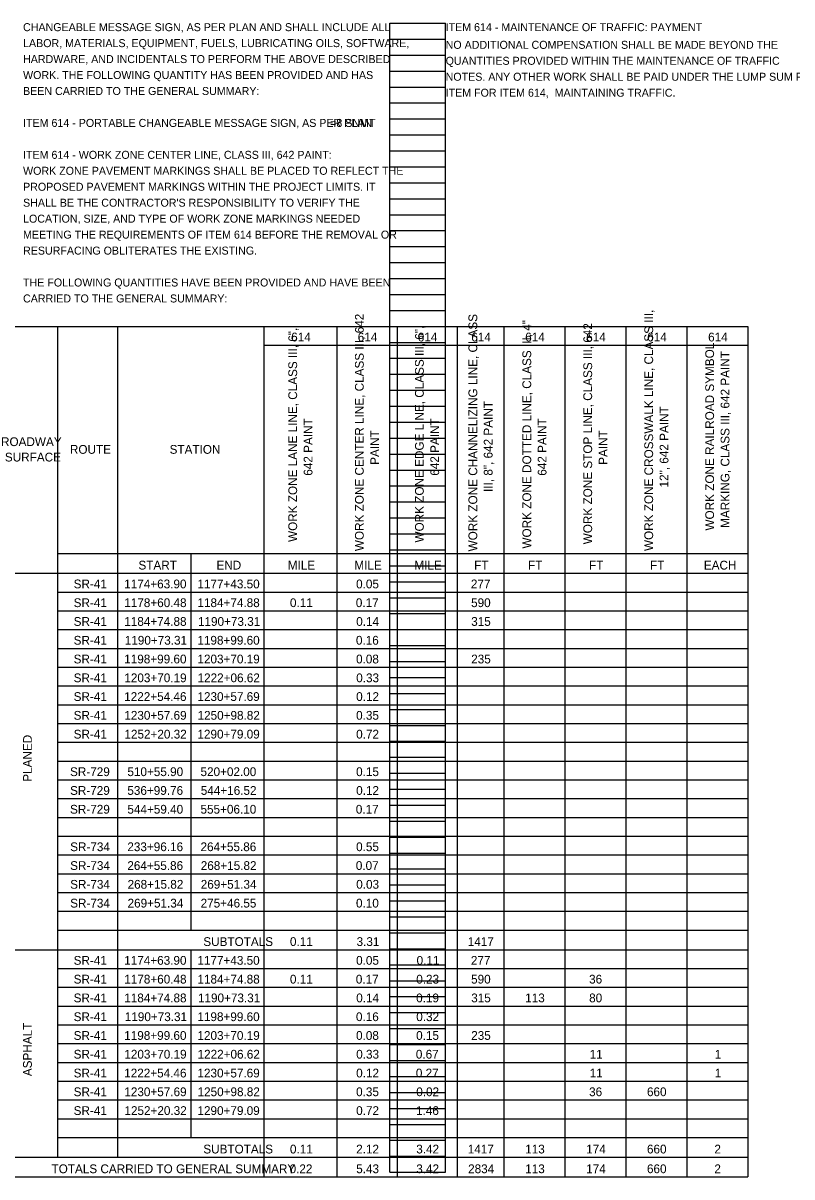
# Model space of a CAD drawing. Extents: x 0 to 37668, y -5 to 18949.
# Drawn here: x 37646.22 to 37659.72, y 18868.37 to 18888.61 of the extents above; entities that cross this region are included whole.
import ezdxf

# ---------------------------------------------------------------- set-up
doc = ezdxf.new("R2010")
doc.units = 0
doc.layers.add('SH_Data', color=7, linetype='Continuous')
doc.layers.add('SH_Text', color=7, linetype='Continuous')

msp = doc.modelspace()

# ---------------------------------------------------------------- linework, layer by layer
at = {"layer": 'SH_Data'}
for p, q in [((37652.661, 18868.45), (37652.661, 18888.61)), ((37652.661, 18888.61), (37653.641, 18888.61)), ((37653.641, 18868.45), (37653.641, 18888.61)), ((37652.661, 18888.33), (37653.641, 18888.33)), ((37652.661, 18888.05), (37653.641, 18888.05)), ((37652.661, 18887.77), (37653.641, 18887.77)), ((37652.661, 18887.49), (37653.641, 18887.49)), ((37652.661, 18887.21), (37653.641, 18887.21)), ((37652.661, 18886.93), (37653.641, 18886.93)), ((37652.661, 18886.65), (37653.641, 18886.65)), ((37652.661, 18886.37), (37653.641, 18886.37)), ((37652.661, 18886.09), (37653.641, 18886.09)), ((37652.661, 18885.81), (37653.641, 18885.81)), ((37652.661, 18885.53), (37653.641, 18885.53)), ((37652.661, 18885.25), (37653.641, 18885.25)), ((37652.661, 18884.97), (37653.641, 18884.97)), ((37652.661, 18884.69), (37653.641, 18884.69)), ((37652.661, 18884.41), (37653.641, 18884.41)), ((37652.661, 18884.13), (37653.641, 18884.13)), ((37652.661, 18883.85), (37653.641, 18883.85)), ((37652.661, 18883.57), (37653.641, 18883.57)), ((37652.661, 18883.29), (37653.641, 18883.29)), ((37652.661, 18883.01), (37653.641, 18883.01)), ((37652.661, 18882.73), (37653.641, 18882.73)), ((37652.661, 18882.45), (37653.641, 18882.45)), ((37652.661, 18882.17), (37653.641, 18882.17)), ((37652.661, 18881.89), (37653.641, 18881.89)), ((37652.661, 18881.61), (37653.641, 18881.61)), ((37652.661, 18881.33), (37653.641, 18881.33)), ((37652.661, 18881.05), (37653.641, 18881.05)), ((37652.661, 18880.77), (37653.641, 18880.77)), ((37652.661, 18880.49), (37653.641, 18880.49)), ((37652.661, 18880.21), (37653.641, 18880.21)), ((37652.661, 18879.93), (37653.641, 18879.93)), ((37652.661, 18879.65), (37653.641, 18879.65)), ((37652.661, 18879.37), (37653.641, 18879.37)), ((37652.661, 18879.09), (37653.641, 18879.09)), ((37652.661, 18878.81), (37653.641, 18878.81)), ((37652.661, 18878.53), (37653.641, 18878.53)), ((37652.661, 18878.25), (37653.641, 18878.25)), ((37652.661, 18877.97), (37653.641, 18877.97)), ((37652.661, 18877.69), (37653.641, 18877.69)), ((37652.661, 18877.41), (37653.641, 18877.41)), ((37652.661, 18877.13), (37653.641, 18877.13)), ((37652.661, 18876.85), (37653.641, 18876.85)), ((37652.661, 18876.57), (37653.641, 18876.57)), ((37652.661, 18876.29), (37653.641, 18876.29)), ((37652.661, 18876.01), (37653.641, 18876.01)), ((37652.661, 18875.73), (37653.641, 18875.73)), ((37652.661, 18875.45), (37653.641, 18875.45)), ((37652.661, 18875.17), (37653.641, 18875.17)), ((37652.661, 18874.89), (37653.641, 18874.89)), ((37652.661, 18874.61), (37653.641, 18874.61)), ((37652.661, 18874.33), (37653.641, 18874.33)), ((37652.661, 18874.05), (37653.641, 18874.05)), ((37652.661, 18873.77), (37653.641, 18873.77)), ((37652.661, 18873.49), (37653.641, 18873.49)), ((37652.661, 18873.21), (37653.641, 18873.21)), ((37652.661, 18872.93), (37653.641, 18872.93)), ((37652.661, 18872.65), (37653.641, 18872.65)), ((37652.661, 18872.37), (37653.641, 18872.37)), ((37652.661, 18872.09), (37653.641, 18872.09)), ((37652.661, 18871.81), (37653.641, 18871.81)), ((37652.661, 18871.53), (37653.641, 18871.53)), ((37652.661, 18871.25), (37653.641, 18871.25)), ((37652.661, 18870.97), (37653.641, 18870.97)), ((37652.661, 18870.69), (37653.641, 18870.69)), ((37652.661, 18870.41), (37653.641, 18870.41)), ((37652.661, 18870.13), (37653.641, 18870.13)), ((37652.661, 18869.85), (37653.641, 18869.85)), ((37652.661, 18869.57), (37653.641, 18869.57)), ((37652.661, 18869.29), (37653.641, 18869.29)), ((37652.661, 18869.01), (37653.641, 18869.01)), ((37652.661, 18868.73), (37653.641, 18868.73)), ((37652.661, 18868.45), (37653.641, 18868.45))]:
    msp.add_line(p, q, dxfattribs=at)
at = {"layer": 'SH_Text'}
for p, q in [((37645.771, 18883.29), (37658.947, 18883.29)), ((37646.825, 18883.29), (37646.825, 18868.713)), ((37647.879, 18883.29), (37647.879, 18868.713)), ((37650.449, 18883.29), (37650.449, 18868.367)), ((37651.733, 18883.29), (37651.733, 18868.367)), ((37652.787, 18883.29), (37652.787, 18868.367)), ((37653.842, 18883.29), (37653.842, 18868.367)), ((37654.665, 18883.29), (37654.665, 18868.367)), ((37655.736, 18883.29), (37655.736, 18868.367)), ((37656.806, 18883.29), (37656.806, 18868.367)), ((37657.877, 18883.29), (37657.877, 18868.367)), ((37658.947, 18883.29), (37658.947, 18868.367)), ((37650.449, 18882.96), (37658.947, 18882.96)), ((37646.825, 18879.304), (37658.947, 18879.304)), ((37649.164, 18879.304), (37649.164, 18872.699)), ((37645.771, 18878.958), (37658.947, 18878.958)), ((37646.825, 18878.629), (37658.947, 18878.629)), ((37646.825, 18878.299), (37658.947, 18878.299)), ((37646.825, 18877.97), (37658.947, 18877.97)), ((37646.825, 18877.64), (37658.947, 18877.64)), ((37646.825, 18877.311), (37658.947, 18877.311)), ((37646.825, 18876.981), (37658.947, 18876.981)), ((37646.825, 18876.652), (37658.947, 18876.652)), ((37646.825, 18876.323), (37658.947, 18876.323)), ((37646.825, 18875.993), (37658.947, 18875.993)), ((37646.825, 18875.664), (37658.947, 18875.664)), ((37646.825, 18875.334), (37658.947, 18875.334)), ((37646.825, 18875.005), (37658.947, 18875.005)), ((37646.825, 18874.676), (37658.947, 18874.676)), ((37646.825, 18874.346), (37658.947, 18874.346)), ((37646.825, 18874.017), (37658.947, 18874.017)), ((37646.825, 18873.687), (37658.947, 18873.687)), ((37646.825, 18873.358), (37658.947, 18873.358)), ((37646.825, 18873.029), (37658.947, 18873.029)), ((37646.825, 18872.699), (37658.947, 18872.699)), ((37645.771, 18872.353), (37658.947, 18872.353)), ((37649.164, 18872.353), (37649.164, 18869.059)), ((37646.825, 18872.024), (37658.947, 18872.024)), ((37646.825, 18871.694), (37658.947, 18871.694)), ((37646.825, 18871.365), (37658.947, 18871.365)), ((37646.825, 18871.036), (37658.947, 18871.036)), ((37646.825, 18870.706), (37658.947, 18870.706)), ((37646.825, 18870.377), (37658.947, 18870.377)), ((37646.825, 18870.047), (37658.947, 18870.047)), ((37646.825, 18869.718), (37658.947, 18869.718)), ((37646.825, 18869.389), (37658.947, 18869.389)), ((37646.825, 18869.059), (37658.947, 18869.059)), ((37645.771, 18868.713), (37658.947, 18868.713)), ((37645.771, 18868.367), (37658.947, 18868.367))]:
    msp.add_line(p, q, dxfattribs=at)

# ---------------------------------------------------------------- texts
for s, height, p in [('CHANGEABLE MESSAGE SIGN, AS PER PLAN AND SHALL INCLUDE ALL ', 0.14, (37646.221, 18888.47)), ('ITEM 614 - MAINTENANCE OF TRAFFIC: PAYMENT', 0.14, (37653.641, 18888.47)), ('LABOR, MATERIALS, EQUIPMENT, FUELS, LUBRICATING OILS, SOFTWARE, ', 0.14, (37646.221, 18888.19)), ('NO ADDITIONAL COMPENSATION SHALL BE MADE BEYOND THE ', 0.14, (37653.641, 18888.16)), ('HARDWARE, AND INCIDENTALS TO PERFORM THE ABOVE DESCRIBED ', 0.14, (37646.221, 18887.91)), ('QUANTITIES PROVIDED WITHIN THE MAINTENANCE OF TRAFFIC ', 0.14, (37653.641, 18887.88)), ('WORK. THE FOLLOWING QUANTITY HAS BEEN PROVIDED AND HAS ', 0.14, (37646.221, 18887.63)), ('NOTES. ANY OTHER WORK SHALL BE PAID UNDER THE LUMP SUM PAY ', 0.14, (37653.641, 18887.6)), ('BEEN CARRIED TO THE GENERAL SUMMARY:', 0.14, (37646.221, 18887.35)), ('ITEM FOR ITEM 614,  MAINTAINING TRAFFIC.', 0.14, (37653.641, 18887.32)), ('ITEM 614 - PORTABLE CHANGEABLE MESSAGE SIGN, AS PER PLAN', 0.14, (37646.221, 18886.79)), ('    =', 0.14, (37651.403, 18886.79)), ('8 SNMT', 0.14, (37651.722, 18886.79)), ('ITEM 614 - WORK ZONE CENTER LINE, CLASS III, 642 PAINT:', 0.14, (37646.221, 18886.23)), ('WORK ZONE PAVEMENT MARKINGS SHALL BE PLACED TO REFLECT THE ', 0.14, (37646.221, 18885.95)), ('PROPOSED PAVEMENT MARKINGS WITHIN THE PROJECT LIMITS. IT ', 0.14, (37646.221, 18885.67)), ("SHALL BE THE CONTRACTOR'S RESPONSIBILITY TO VERIFY THE ", 0.14, (37646.221, 18885.39)), ('LOCATION, SIZE, AND TYPE OF WORK ZONE MARKINGS NEEDED ', 0.14, (37646.221, 18885.11)), ('MEETING THE REQUIREMENTS OF ITEM 614 BEFORE THE REMOVAL OR ', 0.14, (37646.221, 18884.83)), ('RESURFACING OBLITERATES THE EXISTING.', 0.14, (37646.221, 18884.55)), ('THE FOLLOWING QUANTITIES HAVE BEEN PROVIDED AND HAVE BEEN ', 0.14, (37646.221, 18883.99)), ('CARRIED TO THE GENERAL SUMMARY:', 0.14, (37646.221, 18883.71)), ('614', 0.154, (37650.929, 18883.026)), ('614', 0.154, (37652.098, 18883.026)), ('614', 0.154, (37653.152, 18883.026)), ('614', 0.154, (37654.091, 18883.026)), ('614', 0.154, (37655.038, 18883.026)), ('614', 0.154, (37656.109, 18883.026)), ('614', 0.154, (37657.18, 18883.026)), ('614', 0.154, (37658.25, 18883.026)), ('ROADWAY ', 0.154, (37645.834, 18881.19)), ('ROUTE', 0.154, (37647.044, 18881.055)), ('STATION', 0.154, (37648.794, 18881.055)), ('SURFACE', 0.154, (37645.902, 18880.92)), ('START', 0.154, (37648.247, 18879.024)), ('END', 0.154, (37649.617, 18879.024)), ('MILE', 0.154, (37650.869, 18879.024)), ('MILE', 0.154, (37652.038, 18879.024)), ('MILE', 0.154, (37653.092, 18879.024)), ('FT', 0.154, (37654.142, 18879.024)), ('FT', 0.154, (37655.089, 18879.024)), ('FT', 0.154, (37656.16, 18879.024)), ('FT', 0.154, (37657.231, 18879.024)), ('EACH', 0.154, (37658.175, 18879.024)), ('SR-41', 0.154, (37647.109, 18878.694)), ('1174+63.90', 0.154, (37647.997, 18878.694)), ('1177+43.50', 0.154, (37649.282, 18878.694)), ('0.05', 0.154, (37652.069, 18878.694)), ('277', 0.154, (37654.084, 18878.694)), ('SR-41', 0.154, (37647.109, 18878.365)), ('1178+60.48', 0.154, (37647.998, 18878.365)), ('1184+74.88', 0.154, (37649.283, 18878.365)), ('0.11', 0.154, (37650.907, 18878.365)), ('0.17', 0.154, (37652.064, 18878.365)), ('590', 0.154, (37654.088, 18878.365)), ('SR-41', 0.154, (37647.109, 18878.036)), ('1184+74.88', 0.154, (37647.998, 18878.036)), ('1190+73.31', 0.154, (37649.292, 18878.036)), ('0.14', 0.154, (37652.071, 18878.036)), ('315', 0.154, (37654.09, 18878.036)), ('SR-41', 0.154, (37647.109, 18877.706)), ('1190+73.31', 0.154, (37648.007, 18877.706)), ('1198+99.60', 0.154, (37649.282, 18877.706)), ('0.16', 0.154, (37652.066, 18877.706)), ('SR-41', 0.154, (37647.109, 18877.377)), ('1198+99.60', 0.154, (37647.997, 18877.377)), ('1203+70.19', 0.154, (37649.283, 18877.377)), ('0.08', 0.154, (37652.068, 18877.377)), ('235', 0.154, (37654.09, 18877.377)), ('SR-41', 0.154, (37647.109, 18877.047)), ('1203+70.19', 0.154, (37647.999, 18877.047)), ('1222+06.62', 0.154, (37649.285, 18877.047)), ('0.33', 0.154, (37652.071, 18877.047)), ('SR-41', 0.154, (37647.109, 18876.718)), ('1222+54.46', 0.154, (37647.997, 18876.718)), ('1230+57.69', 0.154, (37649.283, 18876.718)), ('0.12', 0.154, (37652.07, 18876.718)), ('SR-41', 0.154, (37647.109, 18876.389)), ('1230+57.69', 0.154, (37647.999, 18876.389)), ('1250+98.82', 0.154, (37649.285, 18876.389)), ('0.35', 0.154, (37652.069, 18876.389)), ('SR-41', 0.154, (37647.109, 18876.059)), ('1252+20.32', 0.154, (37648.001, 18876.059)), ('1290+79.09', 0.154, (37649.283, 18876.059)), ('0.72', 0.154, (37652.07, 18876.059)), ('SR-729', 0.154, (37647.046, 18875.4)), ('510+55.90', 0.154, (37648.053, 18875.4)), ('520+02.00', 0.154, (37649.337, 18875.4)), ('0.15', 0.154, (37652.069, 18875.4)), ('SR-729', 0.154, (37647.046, 18875.071)), ('536+99.76', 0.154, (37648.052, 18875.071)), ('544+16.52', 0.154, (37649.341, 18875.071)), ('0.12', 0.154, (37652.07, 18875.071)), ('SR-729', 0.154, (37647.046, 18874.741)), ('544+59.40', 0.154, (37648.053, 18874.741)), ('555+06.10', 0.154, (37649.337, 18874.741)), ('0.17', 0.154, (37652.064, 18874.741)), ('SR-734', 0.154, (37647.048, 18874.083)), ('233+96.16', 0.154, (37648.052, 18874.083)), ('264+55.86', 0.154, (37649.337, 18874.083)), ('0.55', 0.154, (37652.069, 18874.083)), ('SR-734', 0.154, (37647.048, 18873.753)), ('264+55.86', 0.154, (37648.052, 18873.753)), ('268+15.82', 0.154, (37649.341, 18873.753)), ('0.07', 0.154, (37652.064, 18873.753)), ('SR-734', 0.154, (37647.048, 18873.424)), ('268+15.82', 0.154, (37648.056, 18873.424)), ('269+51.34', 0.154, (37649.341, 18873.424)), ('0.03', 0.154, (37652.071, 18873.424)), ('SR-734', 0.154, (37647.048, 18873.094)), ('269+51.34', 0.154, (37648.056, 18873.094)), ('275+46.55', 0.154, (37649.339, 18873.094)), ('0.10', 0.154, (37652.067, 18873.094)), ('SUBTOTALS', 0.154, (37649.386, 18872.419)), ('0.11', 0.154, (37650.907, 18872.419)), ('3.31', 0.154, (37652.077, 18872.419)), ('1417', 0.154, (37654.029, 18872.419)), ('SR-41', 0.154, (37647.109, 18872.09)), ('1174+63.90', 0.154, (37647.997, 18872.09)), ('1177+43.50', 0.154, (37649.282, 18872.09)), ('0.05', 0.154, (37652.069, 18872.09)), ('0.11', 0.154, (37653.131, 18872.09)), ('277', 0.154, (37654.084, 18872.09)), ('SR-41', 0.154, (37647.109, 18871.76)), ('1178+60.48', 0.154, (37647.998, 18871.76)), ('1184+74.88', 0.154, (37649.283, 18871.76)), ('0.11', 0.154, (37650.907, 18871.76)), ('0.17', 0.154, (37652.064, 18871.76)), ('0.23', 0.154, (37653.125, 18871.76)), ('590', 0.154, (37654.088, 18871.76)), ('36', 0.154, (37656.16, 18871.76)), ('SR-41', 0.154, (37647.109, 18871.431)), ('1184+74.88', 0.154, (37647.998, 18871.431)), ('1190+73.31', 0.154, (37649.292, 18871.431)), ('0.14', 0.154, (37652.071, 18871.431)), ('0.19', 0.154, (37653.123, 18871.431)), ('315', 0.154, (37654.09, 18871.431)), ('113', 0.154, (37655.038, 18871.431)), ('80', 0.154, (37656.161, 18871.431)), ('SR-41', 0.154, (37647.109, 18871.101)), ('1190+73.31', 0.154, (37648.007, 18871.101)), ('1198+99.60', 0.154, (37649.282, 18871.101)), ('0.16', 0.154, (37652.066, 18871.101)), ('0.32', 0.154, (37653.125, 18871.101)), ('SR-41', 0.154, (37647.109, 18870.772)), ('1198+99.60', 0.154, (37647.997, 18870.772)), ('1203+70.19', 0.154, (37649.283, 18870.772)), ('0.08', 0.154, (37652.068, 18870.772)), ('0.15', 0.154, (37653.123, 18870.772)), ('235', 0.154, (37654.09, 18870.772)), ('SR-41', 0.154, (37647.109, 18870.443)), ('1203+70.19', 0.154, (37647.999, 18870.443)), ('1222+06.62', 0.154, (37649.285, 18870.443)), ('0.33', 0.154, (37652.071, 18870.443)), ('0.67', 0.154, (37653.118, 18870.443)), ('11', 0.154, (37656.17, 18870.443)), ('1', 0.154, (37658.367, 18870.443)), ('SR-41', 0.154, (37647.109, 18870.113)), ('1222+54.46', 0.154, (37647.997, 18870.113)), ('1230+57.69', 0.154, (37649.283, 18870.113)), ('0.12', 0.154, (37652.07, 18870.113)), ('0.27', 0.154, (37653.118, 18870.113)), ('11', 0.154, (37656.17, 18870.113)), ('1', 0.154, (37658.367, 18870.113)), ('SR-41', 0.154, (37647.109, 18869.784)), ('1230+57.69', 0.154, (37647.999, 18869.784)), ('1250+98.82', 0.154, (37649.285, 18869.784)), ('0.35', 0.154, (37652.069, 18869.784)), ('0.02', 0.154, (37653.125, 18869.784)), ('36', 0.154, (37656.16, 18869.784)), ('660', 0.154, (37657.176, 18869.784)), ('SR-41', 0.154, (37647.109, 18869.454)), ('1252+20.32', 0.154, (37648.001, 18869.454)), ('1290+79.09', 0.154, (37649.283, 18869.454)), ('0.72', 0.154, (37652.07, 18869.454)), ('1.46', 0.154, (37653.121, 18869.454)), ('SUBTOTALS', 0.154, (37649.386, 18868.779)), ('0.11', 0.154, (37650.907, 18868.779)), ('2.12', 0.154, (37652.07, 18868.779)), ('3.42', 0.154, (37653.125, 18868.779)), ('1417', 0.154, (37654.029, 18868.779)), ('113', 0.154, (37655.038, 18868.779)), ('174', 0.154, (37656.109, 18868.779)), ('660', 0.154, (37657.176, 18868.779)), ('2', 0.154, (37658.36, 18868.779)), ('TOTALS CARRIED TO GENERAL SUMMARY', 0.154, (37646.721, 18868.433)), ('0.22', 0.154, (37650.901, 18868.433)), ('5.43', 0.154, (37652.071, 18868.433)), ('3.42', 0.154, (37653.125, 18868.433)), ('2834', 0.154, (37654.036, 18868.433)), ('113', 0.154, (37655.038, 18868.433)), ('174', 0.154, (37656.109, 18868.433)), ('660', 0.154, (37657.176, 18868.433)), ('2', 0.154, (37658.36, 18868.433))]:
    msp.add_text(s, height=height, dxfattribs=at).set_placement(p)
for s, p in [('WORK ZONE CENTER LINE, CLASS III, 642 ', (37652.203, 18879.347)), ('WORK ZONE CHANNELIZING LINE, CLASS ', (37654.196, 18879.342)), ('WORK ZONE CROSSWALK LINE, CLASS III, ', (37657.284, 18879.349)), ('WORK ZONE LANE LINE, CLASS III, 6", ', (37651.033, 18879.508)), ('WORK ZONE EDGE LINE, CLASS III, 6", ', (37653.257, 18879.498)), ('WORK ZONE DOTTED LINE, CLASS III, 4" ', (37655.143, 18879.392)), ('WORK ZONE STOP LINE, CLASS III, 642 ', (37656.213, 18879.467)), ('WORK ZONE RAILROAD SYMBOL ', (37658.354, 18879.708)), ('MARKING, CLASS III, 642 PAINT', (37658.624, 18879.755)), ('III, 8", 642 PAINT', (37654.465, 18880.385)), ('12", 642 PAINT', (37657.553, 18880.464)), ('642 PAINT', (37651.303, 18880.67)), ('642 PAINT', (37653.526, 18880.67)), ('642 PAINT', (37655.412, 18880.67)), ('PAINT', (37652.472, 18880.861)), ('PAINT', (37656.483, 18880.861)), ('PLANED', (37646.375, 18875.301)), ('ASPHALT', (37646.375, 18870.135))]:
    msp.add_text(s, height=0.154, rotation=90, dxfattribs=at).set_placement(p)

doc.saveas('drawing.dxf')
